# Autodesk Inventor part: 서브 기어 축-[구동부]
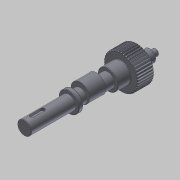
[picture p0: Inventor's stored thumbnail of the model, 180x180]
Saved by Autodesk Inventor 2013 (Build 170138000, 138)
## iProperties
Created: 2018-12
Part Number: 서브 기어 축-[구동부]
Material: 강철, 연강
Document SubType Name: Modeling
Designer: mduedu
Categories: <?xml version="1.0" encoding="UTF-16"?> <MemberInstance><Categories><FamilyTemplate><FamilyTemplateParameter ValueType="xs:double" Id="1" ObjectReferenceKey="da
Density: 7.86 g/cm^3
Mass: 514.749 g
Surface Area: 160.366 cm^2
Volume: 65.4897 cm^3
Author: mduedu
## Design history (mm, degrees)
sketch "Sketch1"
  geometry: C1 r 21.3 at (0, 0)
  constraints: 1 centre point
  dimensions: "d0" = 42.6 diameter of C1 (= da_da)
extrude "Extrusion1" new body sketch "Sketch1" distance "d1" = 20 (= da_b); taper "d2" = 0 deg
workplane "Work Plane2"
sketch "Sketch2"
  geometry: C1 r 21.3 at (0, 0) reference; C2 r 20.5 at (0, 0)
  constraints: 1 centre point, 1 coincident
  dimensions: "d3" = 41 diameter of C2 (= da_dw)
feature "피치 지름" sketch "Sketch2" dims "d4" = 10, "d5" = 0
workplane "Work Plane8"
workplane "Work Plane9"
chamfer "모따기1" distance "d49" = 1; stored, may be unused: second distance "d50" = 2, angle "d51" = 45 deg
sketch "스케치3"
  geometry: C1 r 12.5 at (0, 0); 1 further point
  constraints: 1 centre point, 1 coincident
  dimensions: "d52" = 25 diameter of C1
extrude "돌출2" join sketch "스케치3" distance "d53" = 16; taper "d54" = 0 deg
sketch "스케치4"
  geometry: C1 r 8.5 at (0, 0); 1 further point
  constraints: 1 centre point, 1 coincident
  dimensions: "d55" = 17 diameter of C1
extrude "돌출3" join sketch "스케치4" distance "d56" = 103; taper "d57" = 0 deg
sketch "스케치5"
  geometry: C1 r 7.5 at (0, 0); 1 further point
  constraints: 1 centre point, 1 coincident
  dimensions: "d58" = 15 diameter of C1
extrude "돌출4" join sketch "스케치5" distance "d59" = 16; taper "d60" = 0 deg
sketch "스케치6"
  geometry: C1 r 4 at (0, 0); 1 further point
  constraints: 1 centre point, 1 coincident
  dimensions: "d61" = 8 diameter of C1
extrude "돌출5" join sketch "스케치6" distance "d62" = 7; taper "d63" = 0 deg
chamfer "모따기2" distance "d64" = 0.5; stored, may be unused: second distance "d65" = 2, angle "d66" = 45 deg
fillet "모깎기1" dims "d67" = 0.5
feature "스퍼 기어" dims "da_b" = 20, "da_d" = 41, "da_aw" = 31, "da_da" = 42.6, "da_df" = 39.086, "da_dw" = 41, angle "da_beta" = 0 deg, "da_lefttooth" = 0, "da_righttooth" = 0
node "작업 평면11"
sketch "스케치7"
  geometry: C1 r 11.5 at (0, 3); C2 r 8.5 at (0, 0) reference; 1 further point
  constraints: 1 centre point, 1 tangent, 1 vertical alignment
  dimensions: "d69" = 3 distance of point (0, 0) C1.centre; "d70" = 23 diameter of C1 (derived)
extrude "돌출6" join sketch "스케치7" stored distance "d71" = 20; taper "d72" = 0 deg
node "작업 평면12"
sketch "스케치8"
  geometry: C1 r 12.5 at (0, 0) reference; C2 r 12.5 at (0, 0) reference; 1 further point
extrude "돌출7" join sketch "스케치8" distance "d74" = 5; taper "d75" = 0 deg
chamfer "모따기3" distance "d76" = 0.5; stored, may be unused: second distance "d77" = 2, angle "d78" = 45 deg
sketch "스케치9"
  geometry: L1 (-8, 139)-(8, 139) reference; L2 (0, 139)-(0, 0); L3 (-8.5, 84)-(-8.5, 138.5) reference; L4 (-8.5, 115)-(0, 115); L5 (-8.5, 115)-(-8.5, 113.5); L6 (-8.5, 113.5)-(-7, 115); L7 (-7, 115)-(-8.5, 115)
  constraints: 10 end point, 4 point on line, 2 perpendicular, 1 collinear, 1 midpoint
  dimensions: "d79" = 24 distance between parallel lines of L4 L1; "d80" = 3 diameter of L5.end L4; "d81" = 45 deg angle of L6 L3
revolve "회전1" sketch "스케치9" stored, may be unused: angle "d82" = 90 deg
sketch "스케치10"
  geometry: L1 (-8.5, 116.5)-(-7, 115) reference; L2 (-8.5, 113.5)-(-7, 115) reference; 2 further points
  constraints: 1 coincident
node "작업점1"
node "작업 평면13"
sketch "스케치11"
  geometry: L1 (-2.5, 93.5)-(-2.5, 80.5); L2 (2.5, 80.5)-(2.5, 93.5); L3 (-8, 103)-(8, 103) reference; A1 r 2.5 centre (0, 93.5) between (2.5, 93.5) and (-2.5, 93.5); A2 r 2.5 centre (0, 80.5) between (-2.5, 80.5) and (2.5, 80.5); 1 further point
  constraints: 4 end point, 4 point on circle, 4 tangent, 2 centre point, 2 vertical alignment, 1 parallel
  dimensions: "d83" = 7 distance edge to line of A1 L3; "d84" = 18 dimension on A2 A1; "d85" = 5 distance between parallel lines of L1 L2
extrude "돌출8" cut sketch "스케치11" distance "d86" = 3; taper "d87" = 0 deg
sketch "스케치12" dims "d88" = 32
  geometry: C1 r 0.5 at (0, -16); 2 further points
  constraints: 2 vertical alignment, 1 centre point, 1 coincident, 2 other
  dimensions: "d89" = 1 diameter of C1
extrude "돌출9" join sketch "스케치12" distance "d90" = 0.3; taper "d91" = 0 deg
sketch "스케치13"
  geometry: C1 r 11.5 at (0, 3) reference; 1 further point
  node "절단 모서리 투영1"
body "Solid1"
body "Srf1"
node "투영된 루프1"
other parameters: "d16" = 31 (= da_aw), "d17" = 0, "d34" = 0.76624 (computed from da_z), "d39" = 0, "d41" = 0, "d43" = 31 (= da_aw), "d46" = 31 (= da_aw), "d47" = 0, "d48" = 0, "d68" = 24, "d73" = 48
